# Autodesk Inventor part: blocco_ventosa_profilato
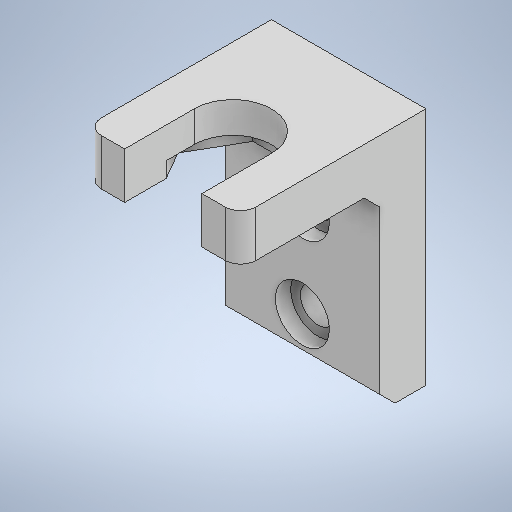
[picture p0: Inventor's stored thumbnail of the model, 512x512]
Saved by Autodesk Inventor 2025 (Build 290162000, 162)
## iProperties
Created: 2026-03
Part Number: blocco_ventosa_profilato
Material: Generico
Document SubType Name: Modeling
Designer: Ryzen5700u
Density: 1 g/cm^3
Appearance: Default
Author: Ryzen5700u
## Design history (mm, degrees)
sketch "Schizzo1"
  geometry: L1 (10, 15)-(-10, 15); L2 (-10, 15)-(-10, -15); L3 (-10, -15)-(10, -15); L4 (10, -15)-(10, 15); L5 (10, 15)-(-10, -15); L6 (-10, 15)-(10, -15); L7 (10, 0)-(-10, 0); L8 (10, 9)-(-10, 9); L9 (5, 0)-(5, 9); L10 (-5, 0)-(-5, 9); A1 r 5 centre (0, 0) between (5, 0) and (-5, 0); 4 further points
  constraints: 20 end point, 6 point on line, 5 midpoint, 4 perpendicular, 2 parallel, 2 point on circle, 1 centre point, 1 coincident, 1 horizontal, 1 tangent
  dimensions: "d0" = 10 diameter of A1; "d1" = 20 distance of L3.end L2.end; "d2" = 30 distance of L2.end L1.end; "d17" = 9 distance from line of point (0, 0) L8
extrude "Estrusione1" new body sketch "Schizzo1" distance "d3" = 6; taper "d4" = 0 deg
sketch "Schizzo2"
  geometry: L1 (-10, 15)-(10, 15); L2 (10, 15)-(10, 10); L3 (10, 10)-(-10, 10); L4 (-10, 10)-(-10, 15); 8 further points
  constraints: 8 end point, 2 parallel, 1 horizontal, 1 perpendicular, 3 other
  dimensions: "d5" = 5 distance of L1.end L2.end
extrude "Estrusione2" join sketch "Schizzo2" distance "d6" = 15; taper "d7" = 0 deg
sketch "Schizzo3"
  geometry: L1 (0, 15)-(20, 15) reference; L2 (3, 0)-(14, 0) reference; L3 (10, 15)-(10, -6); 4 further points
  constraints: 2 end point, 2 point on line, 1 midpoint, 1 perpendicular
  dimensions: "d8" = 16 distance from line of L1 point (10, -1); "d9" = 12 distance of point (10, -1) point (10, -13)
hole "Foro1" sketch "Schizzo3" at (10, -1), (10, -13) diameter "d10" = 3.4; stored, may be unused: countersink angle "d14" = 90 deg, drill point angle "d16" = 118 deg; dims "d11" = 6, "d12" = 6.5, "d13" = 3.4, "d15" = 8
fillet "Raccordo1" dims "d18" = 2
sketch "Schizzo4"
  geometry: L1 (0, 0)-(20, 0) reference; L2 (10, 0)-(10, -2); C1 r 0.5 at (10, -2); 3 further points
  constraints: 2 end point, 1 centre point, 1 coincident, 1 midpoint, 1 vertical
  dimensions: "d22" = 2 distance of L2.start L2.end; "d23" = 1 diameter of C1
extrude "Estrusione3" cut sketch "Schizzo4" distance "d24" = 30; taper "d25" = 0 deg
fillet "Raccordo3" dims "d27" = 2
sketch "Schizzo6"
  geometry: L1 (3.464, 6)-(-3.464, 6) reference; L2 (-3.464, 6)-(-6.928, 0) reference; L3 (-6.928, 0)-(-3.464, -6) reference; L4 (-3.464, -6)-(3.464, -6) reference; L5 (3.464, -6)-(6.928, 0) reference; L6 (6.928, 0)-(3.464, 6) reference; L7 (-3.551, -6.15)-(-7.101, 0); L8 (-7.101, 0)-(-3.551, 6.15); L9 (-3.551, 6.15)-(3.551, 6.15); L10 (3.551, 6.15)-(7.101, 0); L11 (7.101, 0)-(3.551, -6.15); L12 (3.551, -6.15)-(-3.551, -6.15); C1 r 4 at (0, 0) reference; 1 further point
  constraints: 12 end point, 5 other
  dimensions: "d39" = 0.15 distance between parallel lines of L3 L7
extrude "Estrusione4" cut sketch "Schizzo6" distance "d40" = 2; taper "d41" = 0 deg
sketch "Schizzo7"
  geometry: L1 (-10, -15)-(-10, 7) reference; L2 (10, 7)-(10, -15) reference; L3 (-10, -15)-(10, -15); L4 (10, -15)-(10, -9); L5 (10, -9)-(-10, -9); L6 (-10, -9)-(-10, -15); 3 further points
  constraints: 8 end point, 2 parallel, 1 horizontal, 1 perpendicular, 1 point on line
  dimensions: "d42" = 6 distance of L4.end L3.end
extrude "Estrusione5" join sketch "Schizzo7" distance "d43" = 25; taper "d44" = 0 deg
chamfer "Smusso2" distance "d45" = 2; stored, may be unused: second distance "d46" = 2, angle "d47" = 45 deg
sketch "Schizzo8"
  geometry: L1 (20, 0)-(0, 0) reference; 4 further points
  constraints: 1 midpoint
  dimensions: "d48" = 12 distance of point (10, 6) point (10, 18); "d49" = 6 distance of point (10, 0) point (10, 6)
hole "Foro3" sketch "Schizzo8" at (10, 18), (10, 6) diameter "d50" = 4.5; stored, may be unused: countersink angle "d54" = 90 deg, drill point angle "d56" = 118 deg; dims "d51" = 6, "d52" = 7, "d53" = 2, "d55" = 25
chamfer "Smusso3" distance "d57" = 2; stored, may be unused: second distance "d58" = 2, angle "d59" = 45 deg
node "Solido1"
node "Riferimento1"
